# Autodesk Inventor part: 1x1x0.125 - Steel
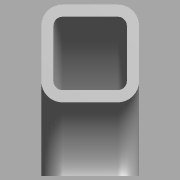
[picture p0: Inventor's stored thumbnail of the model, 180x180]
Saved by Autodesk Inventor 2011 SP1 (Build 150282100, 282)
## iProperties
Created: 2011-03
Part Number: 1x1x0.125 - Steel
Material: Default
Document SubType Name: Modeling
Designer: bamfomg
Density: 1 g/cm^3
Author: bamfomg
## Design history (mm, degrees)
derived "Square Tube Corners.ipt" dims "d2" = 12.7, "d3" = 12.7, "d6" = 3.175, "d7" = 3.175, "d8" = 3.175, "d12" = 90 deg, "d16" = 1.5875, "d18" = 30 deg, "ID_Rad" = 2.38125, "OD_Rad" = 5.55625, "Side_One" = 25.4, "Side_Two" = 25.4, "Thickness" = 3.175, "Bend_IDRad" = 19.05, "Bevel_Angl" = 30 deg, "Bevel_Dist" = 1.5875
body "Solid1"
feature "Solid1::Square Tube Corners.ipt" dims "d2" = 12.7, "d3" = 12.7, "d6" = 3.175, "d7" = 3.175, "d8" = 3.175, "d12" = 90 deg, "d16" = 1.5875, "d18" = 30 deg, "ID_Rad" = 2.38125, "OD_Rad" = 5.55625, "Side_One" = 25.4, "Side_Two" = 25.4, "Thickness" = 3.175, "Bend_IDRad" = 19.05, "Bevel_Angl" = 30 deg, "Bevel_Dist" = 1.5875, "ScaleForDerivedMember" = 10
tag "TaggingFeature1"
